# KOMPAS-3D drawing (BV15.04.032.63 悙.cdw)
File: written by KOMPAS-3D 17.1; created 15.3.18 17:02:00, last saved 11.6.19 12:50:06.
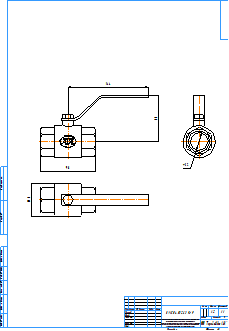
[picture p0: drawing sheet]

Sheet 1: A2, portrait

Title block, sheet 1: name: BV15.04.032.63 Р/Р; material: Внимание! Данный продукт является объектом авторского права ООО «Торговый Дом АДЛ». / Запрещается изменение, копирование, распространение / (в том числе путем копирования на другие сайты и ресурсы в Интернете) / или любое иное использование информации и объектов без предварительного / согласия правообладателя (ООО «Торговый Дом АДЛ»).; mass: 1,2; sheets: 1; organisation: ООО "Торговый дом АДЛ"; sheet format: A2; stored path: \\adlc.lan\data\АДЛ_ПКД\3D-модели\ADL production\Краны шаровые серии BV\BV15\KOMPAS 2D\BV15.04.032.63 РР.cdw

Views: Вид 1, Проекционный вид 2, Проекционный вид 3
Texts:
  kka
  adl
Dimensions and other numbers on the sheet: 98; 144; 82; 32; 57,6; 1:1; 1; 1,2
